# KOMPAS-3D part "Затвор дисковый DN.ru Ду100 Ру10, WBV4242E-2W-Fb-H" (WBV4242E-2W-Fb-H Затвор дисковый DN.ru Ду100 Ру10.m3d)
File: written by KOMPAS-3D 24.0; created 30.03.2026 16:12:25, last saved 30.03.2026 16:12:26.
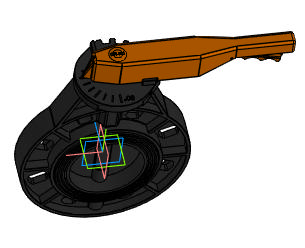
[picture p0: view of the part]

Document properties: Автор: R2D2; Полное имя файла: E:\Работа\Зайцев\WBV4242E-2W-Fb-H Затвор дисковый DN.ru Ду50-200 Ру10\DN100\WBV4242E-2W-Fb-H Затвор дисковый DN.ru Ду100 Ру10.m3d

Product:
- Part/product: Затвор дисковый DN.ru Ду100 Ру10  | designation WBV4242E-2W-Fb-H
    Масса: 2.44
    Раздел спецификации: Прочие изделия
    Примечание: D050-81200

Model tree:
1. Операция без истории:1

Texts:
  WBV4242E-2W-Fb-H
